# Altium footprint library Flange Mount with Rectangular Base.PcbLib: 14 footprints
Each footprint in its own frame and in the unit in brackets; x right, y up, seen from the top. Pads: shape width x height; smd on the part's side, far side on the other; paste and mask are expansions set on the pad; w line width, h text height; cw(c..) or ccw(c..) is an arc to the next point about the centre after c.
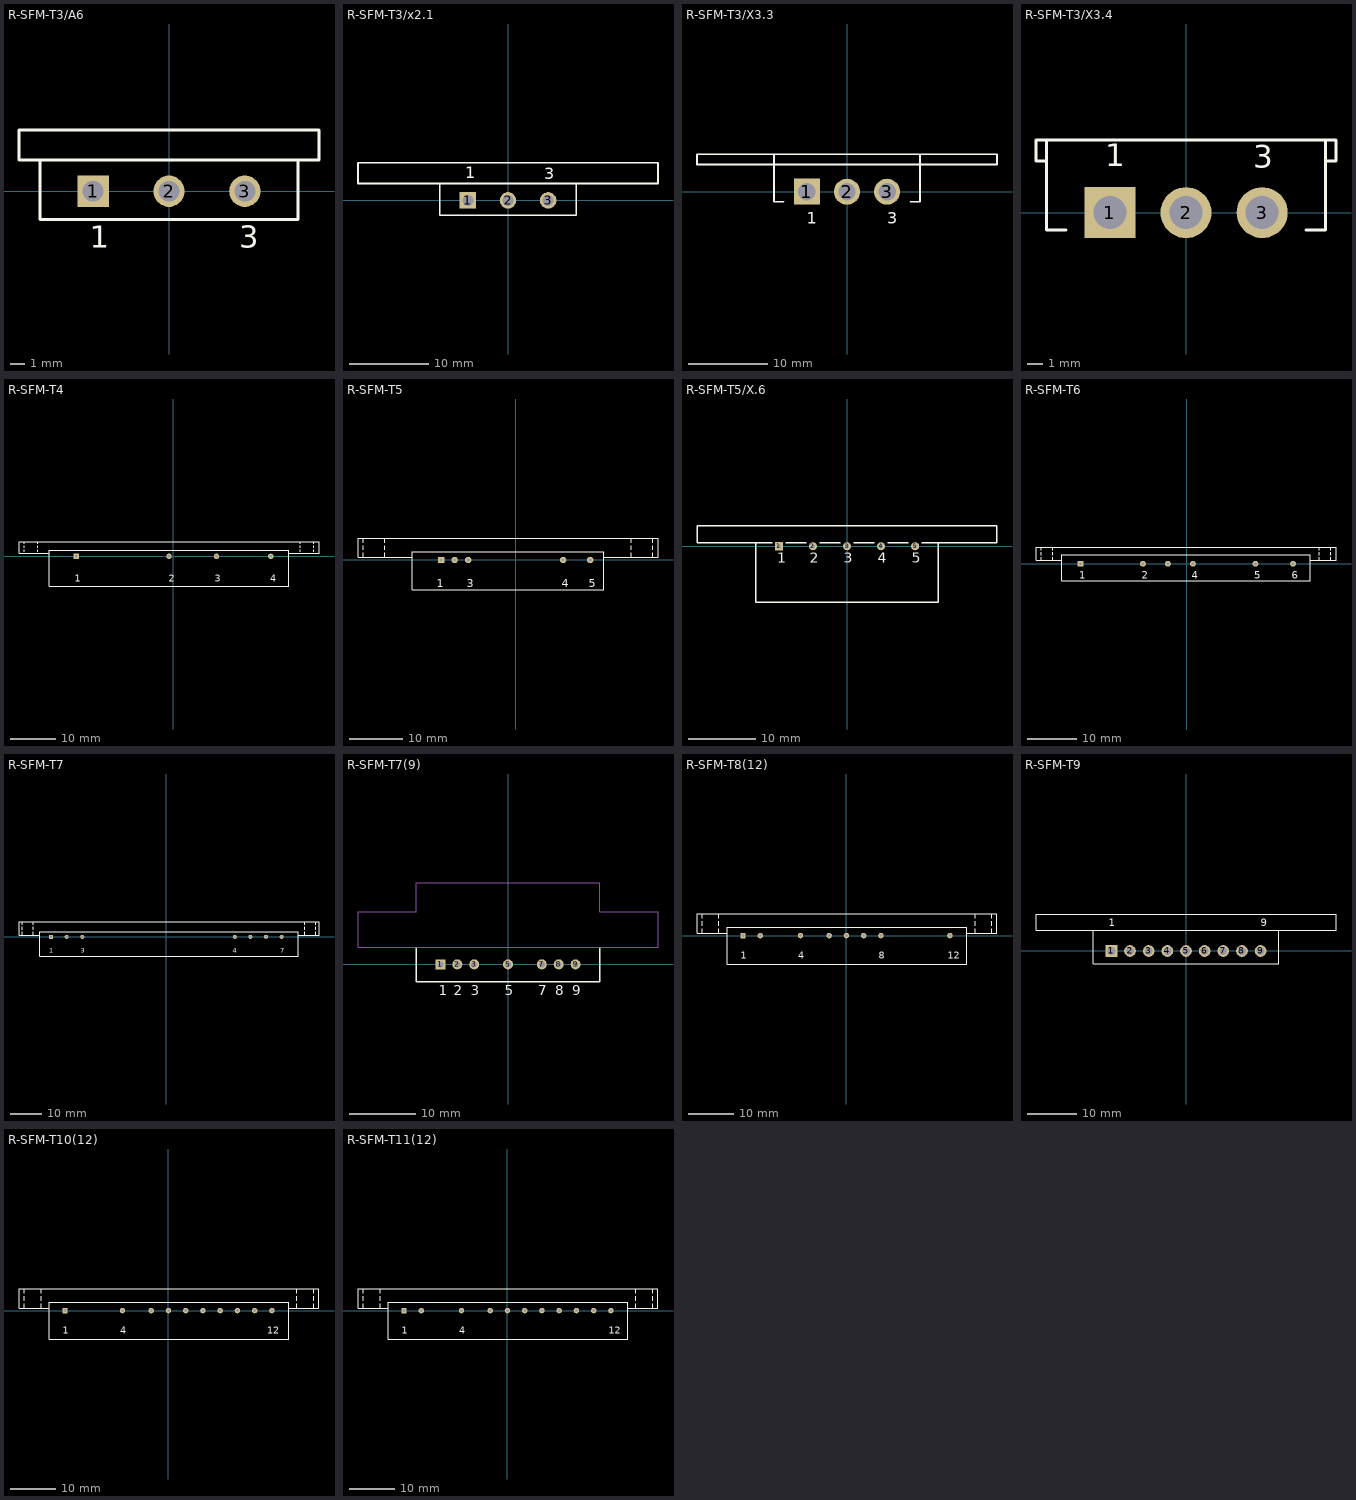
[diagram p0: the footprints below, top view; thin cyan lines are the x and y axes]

## R-SFM-T3/A6 [mm]
pads (3):
  rect 2.1x2.1 hole 1.4: 1(-5.08,0)
  round 2.1 hole 1.4: 2(0,0) 3(5.08,0)
Top Overlay:
  lines w0.2: -8.65,2.1 -8.65,-1.9 8.65,-1.9 8.65,2.1 ; -10.05,2.1 10.05,2.1 10.05,4.1 -10.05,4.1 -10.05,2.1
  text "1" at -5.3,-3.8 h1.5
  text "3" at 4.7,-3.8 h1.5

## R-SFM-T3/x2.1 [mm]
pads (3):
  rect 2.1x2.1 hole 1.4: 1(-5.08,0)
  round 2.1 hole 1.4: 2(0,0) 3(5.08,0)
Top Overlay:
  lines w0.2: -8.65,2.15 -8.65,-1.85 8.65,-1.85 8.65,2.15 ; -19,2.15 -19,4.75 19,4.75 19,2.15 -19,2.15
  text "1" at -5.4,2.8 h1.5
  text "3" at 4.6,2.7 h1.5

## R-SFM-T3/X3.3 [mm]
pads (3):
  rect 3.3x3.3 hole 2.2: 1(-5.08,0)
  round 3.3 hole 2.2: 2(0,0) 3(5.08,0)
Top Overlay:
  lines w0.2: -9.25,4.75 -9.25,-1.25 -8,-1.25 ; 8,-1.25 9.25,-1.25 9.25,4.75 ; -19,3.45 -19,4.75 19,4.75 19,3.45 -19,3.45
  text "1" at -5.08,-4.064 h1.5
  text "3" at 5.08,-4.064 h1.5

## R-SFM-T3/X3.4 [mm]
pads (3):
  rect 3.4x3.4 hole 2.2: 1(-5.08,0)
  round 3.4 hole 2.2: 2(0,0) 3(5.08,0)
Top Overlay:
  lines w0.2: -9.3,3.45 -10,3.45 -10,4.85 10,4.85 10,3.45 9.3,3.45 ; -9.3,4.85 -9.3,-1.15 -8,-1.15 ; 8,-1.15 9.3,-1.15 9.3,4.85
  text "3" at 4.5,3 h1.5
  text "1" at -5.4,3.1 h1.5

## R-SFM-T4 [mm]
pads (4):
  rect 1.2x1.2 hole 0.6: 1(-21.5,0)
  round 1.2 hole 0.6: 2(-0.99,0) 3(9.5,0) 4(21.5,0)
Top Overlay:
  lines w0.2: -33.01,0.964 -33.01,1.464 ; -33.01,1.864 -33.01,2.364 ; -33.01,2.75 -33.01,3.25 ; -30.01,0.964 -30.01,1.464 ; -30.01,1.864 -30.01,2.364 ; -30.01,2.75 -30.01,3.25 ; -27.44,0.65 -34.14,0.65 -34.14,3.25 32.16,3.25 32.16,0.65 25.46,0.65 ; 28.03,0.964 28.03,1.464 ; 28.03,1.864 28.03,2.364 ; 28.03,2.75 28.03,3.25 ; 31.03,0.964 31.03,1.464 ; 31.03,1.864 31.03,2.364 ; 31.03,2.75 31.03,3.25 ; -27.44,-6.65 -27.44,1.35 25.46,1.35 25.46,-6.65 -27.44,-6.65
  text "1" at -21.844,-5.588 h1.5
  text "2" at -1.016,-5.588 h1.5
  text "3" at 9.144,-5.588 h1.5
  text "4" at 21.336,-5.588 h1.5

## R-SFM-T5 [mm]
pads (5):
  rect 1.2x1.2 hole 0.6: 1(-13.97,0)
  round 1.2 hole 0.6: 2(-11.43,0) 3(-8.89,0) 4(8.89,0) 5(13.97,0)
Top Overlay:
  lines w0.2: -28.53,0.55 -28.53,1.35 ; -28.53,1.9 -28.53,2.7 ; -28.53,3.25 -28.53,4.05 ; -24.53,0.55 -24.53,1.35 ; -24.53,1.9 -24.53,2.7 ; -24.53,3.25 -24.53,4.05 ; -19.38,0.55 -29.53,0.55 -29.53,4.05 26.67,4.05 26.67,0.55 16.52,0.55 ; 21.67,0.55 21.67,1.35 ; 21.67,1.9 21.67,2.7 ; 21.67,3.25 21.67,4.05 ; 25.67,0.55 25.67,1.35 ; 25.67,1.9 25.67,2.7 ; 25.67,3.25 25.67,4.05 ; -19.38,-5.55 16.52,-5.55 16.52,1.55 -19.38,1.55 -19.38,-5.55
  text "1" at -14.732,-5.08 h1.5
  text "3" at -9.144,-5.08 h1.5
  text "4" at 8.636,-5.08 h1.5
  text "5" at 13.716,-5.08 h1.5

## R-SFM-T5/X.6 [mm]
pads (5):
  rect 1.2x1.2 hole 0.6: 1(-10.16,0)
  round 1.2 hole 0.6: 2(-5.08,0) 3(0,0) 4(5.08,0) 5(10.16,0)
Top Overlay:
  lines w0.2: -13.65,0.55 -13.65,-8.35 13.65,-8.35 13.65,0.55 ; -11.16,0.55 -22.4,0.55 -22.4,3.05 22.4,3.05 22.4,0.55 11.16,0.55 ; -9.16,0.55 -6.08,0.55 ; -4.08,0.55 -1,0.55 ; 6.08,0.55 9.16,0.55 ; 1,0.55 4.08,0.55 1,0.55
  text "5" at 9.66,-2.475 h1.5
  text "1" at -10.41,-2.475 h1.5
  text "2" at -5.58,-2.475 h1.5
  text "3" at -0.5,-2.475 h1.5
  text "4" at 4.58,-2.475 h1.5

## R-SFM-T6 [mm]
pads (6):
  rect 1.2x1.2 hole 0.6: 1(-21.59,0)
  round 1.2 hole 0.6: 2(-8.89,0) 3(-3.81,0) 4(1.27,0) 5(13.97,0) 6(21.59,0)
Top Overlay:
  lines w0.2: -29.55,0.75 -29.55,1.35 ; -29.55,1.75 -29.55,2.35 ; -29.55,2.75 -29.55,3.35 ; -27.15,0.75 -27.15,1.35 ; -27.15,1.75 -27.15,2.35 ; -27.15,2.75 -27.15,3.35 ; -25.385,0.75 -30.585,0.75 -30.585,3.35 30.315,3.35 30.315,0.75 25.115,0.75 ; 26.88,0.75 26.88,1.35 ; 26.88,1.75 26.88,2.35 ; 26.88,2.75 26.88,3.35 ; 29.28,0.75 29.28,1.35 ; 29.28,1.75 29.28,2.35 ; 29.28,2.75 29.28,3.35 ; -25.385,-3.45 25.115,-3.45 25.115,1.85 -25.385,1.85 -25.385,-3.45
  text "1" at -21.844,-3.048 h1.5
  text "2" at -9.144,-3.048 h1.5
  text "4" at 1.016,-3.048 h1.5
  text "5" at 13.716,-3.048 h1.5
  text "6" at 21.336,-3.048 h1.5

## R-SFM-T7 [mm]
pads (7):
  rect 1.3x1.3 hole 0.7: 1(-36.99,0)
  round 1.3 hole 0.7: 2(-31.99,0) 3(-26.99,0) 4(21.99,0) 5(26.99,0) 6(31.99,0) 7(36.99,0)
Top Overlay:
  lines w0.2: -46.3,0.65 -46.3,1.65 ; -46.3,2.25 -46.3,3.25 ; -46.3,3.85 -46.3,4.85 ; -42.78,0.65 -42.78,1.65 ; -42.78,2.25 -42.78,3.25 ; -42.78,3.85 -42.78,4.85 ; -40.705,0.55 -47.3,0.55 -47.3,4.85 49,4.85 49,0.55 42.395,0.55 ; 44.48,0.65 44.48,1.65 ; 44.48,2.25 44.48,3.25 ; 44.48,3.85 44.48,4.85 ; 48,0.65 48,1.65 ; 48,2.25 48,3.25 ; 48,3.85 48,4.85 ; -40.705,-6.25 -40.705,1.674 42.395,1.674 42.395,-6.25 -40.705,-6.25
  text "7" at 36.576,-5.08 h1.5
  text "4" at 21.336,-5.08 h1.5
  text "3" at -27.432,-5.08 h1.5
  text "1" at -37.592,-5.08 h1.5

## R-SFM-T7(9) [mm]
pads (7):
  rect 1.5x1.5 hole 0.9: 1(-10.16,0)
  round 1.5 hole 0.9: 2(-7.62,0) 3(-5.08,0) 5(0,0) 7(5.08,0) 8(7.62,0) 9(10.16,0)
Top Overlay:
  lines w0.2: -13.8,2.45 -13.8,-2.65 13.8,-2.65 13.8,2.45
  text "9" at 9.66,-4.625 h1.5
  text "8" at 7.12,-4.625 h1.5
  text "5" at -0.5,-4.625 h1.5
  text "1" at -10.41,-4.625 h1.5
  text "2" at -8.12,-4.625 h1.5
  text "3" at -5.58,-4.625 h1.5
  text "7" at 4.58,-4.625 h1.5
Mechanical 1:
  lines w0.1: -22.55,2.54 -22.55,7.935 -13.8,7.935 -13.8,12.25 13.8,12.25 13.8,7.935 22.55,7.935 22.55,2.54 ; -22.55,2.55 22.55,2.55

## R-SFM-T8(12) [mm]
pads (8):
  rect 1.2x1.2 hole 0.6: 1(-22.86,0)
  round 1.2 hole 0.6: 2(-19.05,0) 4(-10.16,0) 5(-3.81,0) 6(0,0) 7(3.81,0) 8(7.62,0) 12(22.86,0)
Top Overlay:
  lines w0.2: -31.88,0.55 -31.88,1.55 ; -31.88,2.2 -31.88,3.2 ; -31.88,3.85 -31.88,4.85 ; -28.18,0.55 -28.18,1.55 ; -28.18,2.2 -28.18,3.2 ; -28.18,3.85 -28.18,4.85 ; -26.38,0.55 -33.03,0.55 -33.03,4.85 33.27,4.85 33.27,0.55 26.62,0.55 ; 28.42,0.55 28.42,1.55 ; 28.42,2.2 28.42,3.2 ; 28.42,3.85 28.42,4.85 ; 32.12,0.55 32.12,1.55 ; 32.12,2.2 32.12,3.2 ; 32.12,3.85 32.12,4.85 ; -26.38,-6.35 -26.38,1.85 26.62,1.85 26.62,-6.35 -26.38,-6.35
  text "1" at -23.368,-5.08 h1.5
  text "8" at 7.112,-5.08 h1.5
  text "12" at 22.352,-5.08 h1.5
  text "4" at -10.668,-5.08 h1.5

## R-SFM-T9 [mm]
pads (9):
  rect 2.4x2.4 hole 1.6: 1(-15.24,0)
  round 2.4 hole 1.6: 2(-11.43,0) 3(-7.62,0) 4(-3.81,0) 5(0,0) 6(3.81,0) 7(7.62,0) 8(11.43,0) 9(15.24,0)
Top Overlay:
  lines w0.2: -18.95,4.25 -18.95,-2.65 18.95,-2.65 18.95,4.25 ; -30.65,4.25 -30.65,7.55 30.65,7.55 30.65,4.25 -30.65,4.25
  text "1" at -15.748,5.08 h1.5
  text "9" at 15.24,5.08 h1.5

## R-SFM-T10(12) [mm]
pads (10):
  rect 1.2x1.2 hole 0.6: 1(-22.86,0)
  round 1.2 hole 0.6: 4(-10.16,0) 5(-3.81,0) 6(0,0) 7(3.81,0) 8(7.62,0) 9(11.43,0) 10(15.24,0) 11(19.05,0) 12(22.86,0)
Top Overlay:
  lines w0.2: -31.88,0.55 -31.88,1.55 ; -31.88,2.2 -31.88,3.2 ; -31.88,3.85 -31.88,4.85 ; -28.13,0.55 -28.13,1.55 ; -28.13,2.2 -28.13,3.2 ; -28.13,3.85 -28.13,4.85 ; -26.38,0.55 -33.03,0.55 -33.03,4.85 33.27,4.85 33.27,0.55 26.62,0.55 ; 28.37,0.55 28.37,1.55 ; 28.37,2.2 28.37,3.2 ; 28.37,3.85 28.37,4.85 ; 32.12,0.55 32.12,1.55 ; 32.12,2.2 32.12,3.2 ; 32.12,3.85 32.12,4.85 ; -26.38,-6.35 -26.38,1.85 26.62,1.85 26.62,-6.35 -26.38,-6.35
  text "12" at 21.844,-5.08 h1.5
  text "4" at -10.668,-5.08 h1.5
  text "1" at -23.368,-5.08 h1.5

## R-SFM-T11(12) [mm]
pads (11):
  rect 1.2x1.2 hole 0.6: 1(-22.86,0)
  round 1.2 hole 0.6: 2(-19.05,0) 4(-10.16,0) 5(-3.81,0) 6(0,0) 7(3.81,0) 8(7.62,0) 9(11.43,0) 10(15.24,0) 11(19.05,0) 12(22.86,0)
Top Overlay:
  lines w0.2: -31.88,0.55 -31.88,1.55 ; -31.88,2.2 -31.88,3.2 ; -31.88,3.85 -31.88,4.85 ; -28.13,0.55 -28.13,1.55 ; -28.13,2.2 -28.13,3.2 ; -28.13,3.85 -28.13,4.85 ; -26.38,0.55 -33.03,0.55 -33.03,4.85 33.27,4.85 33.27,0.55 26.62,0.55 ; 28.37,0.55 28.37,1.55 ; 28.37,2.2 28.37,3.2 ; 28.37,3.85 28.37,4.85 ; 32.12,0.55 32.12,1.55 ; 32.12,2.2 32.12,3.2 ; 32.12,3.85 32.12,4.85 ; -26.38,-6.35 -26.38,1.85 26.62,1.85 26.62,-6.35 -26.38,-6.35
  text "12" at 22.352,-5.08 h1.5
  text "4" at -10.668,-5.08 h1.5
  text "1" at -23.368,-5.08 h1.5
